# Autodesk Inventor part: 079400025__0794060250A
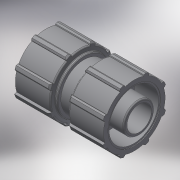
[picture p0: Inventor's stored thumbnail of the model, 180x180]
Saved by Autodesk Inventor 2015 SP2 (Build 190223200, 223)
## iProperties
Created: 2017-04
Part Number: 079400025__0794060250A
Material: Generic
Description: PLASSON MODULAR ADAPTOR 25
Document SubType Name: Modeling
Designer: KIM
Mass: 81.7203 g
Surface Area: 308.949 cm^2
Volume: 81.7203 cm^3
Density: 1 g/cm^3
Appearance: Default
Author: KIM
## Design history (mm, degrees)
derived "07940.ipt"
feature "Solid1::07940.ipt"
tag "TaggingFeature1"
body "Solid1"
other parameters: "d7" = 54, "d8" = 43.2, "d9" = 25, "d15" = 40.5, "d17" = 32, "d43" = 100 deg, "d46" = 50.22, "d47" = 35 deg, "d48" = 17.5 deg, "d50" = 0, "d52" = 360 deg, "d54" = 1.08, "d57" = 1.08, "d68" = 28.8, "d69" = 0.5, "d70" = 2.88, "d71" = 5, "d74" = 36, "d75" = 37.8, "d76" = 0.54, "d77" = 1.08, "d79" = 360 deg, "d81" = 1.08, "d82" = 16, "d_" = 25, "E_" = 54
